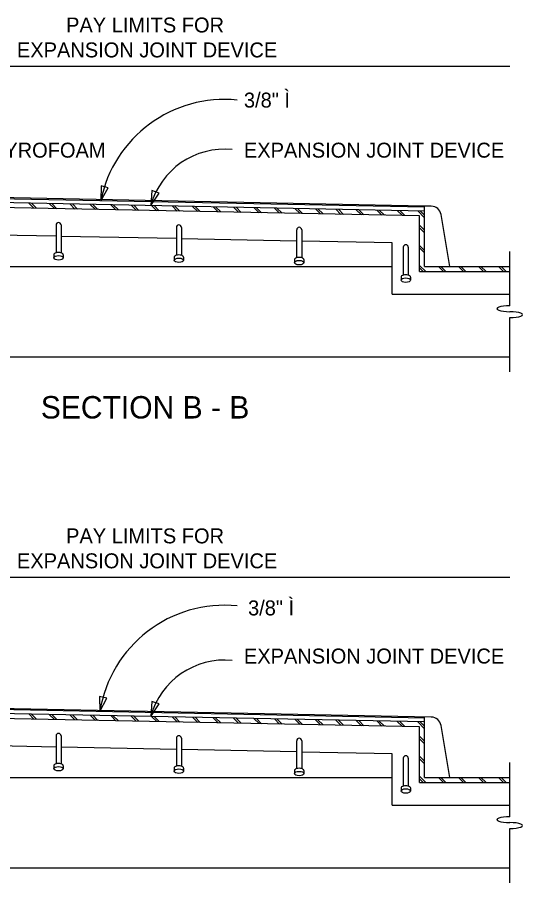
# Model space of a CAD drawing. Extents: x 19590 to 20151, y 19944 to 20103.
# Drawn here: x 19659.09 to 19674.83, y 20050.39 to 20077.38 of the extents above; entities that cross this region are included whole.
import ezdxf

# ---------------------------------------------------------------- set-up
doc = ezdxf.new("R2010")
doc.units = 0
doc.layers.add('DETAIL_PR', color=7, linetype='Continuous')
doc.layers.add('DETAIL_TEXT_DIMEN_PR', color=7, linetype='Continuous')

msp = doc.modelspace()

# ---------------------------------------------------------------- linework, layer by layer
at = {"layer": 'DETAIL_PR'}
for p, q in [((19671.778, 20071.498), (19655.216, 20071.829)), ((19671.778, 20071.459), (19655.216, 20071.79)), ((19671.778, 20071.342), (19655.216, 20071.673)), ((19671.622, 20071.188), (19655.216, 20071.517)), ((19659.605, 20071.429), (19659.446, 20071.588)), ((19659.685, 20071.427), (19659.525, 20071.587)), ((19660.243, 20071.416), (19660.083, 20071.576)), ((19660.323, 20071.414), (19660.163, 20071.574)), ((19660.881, 20071.403), (19660.721, 20071.563)), ((19660.96, 20071.402), (19660.801, 20071.561)), ((19661.518, 20071.391), (19661.359, 20071.55)), ((19661.598, 20071.389), (19661.439, 20071.548)), ((19662.156, 20071.378), (19661.997, 20071.537)), ((19662.236, 20071.376), (19662.076, 20071.536)), ((19662.794, 20071.365), (19662.634, 20071.524)), ((19662.874, 20071.363), (19662.714, 20071.523)), ((19663.432, 20071.352), (19663.272, 20071.512)), ((19663.511, 20071.351), (19663.352, 20071.51)), ((19664.069, 20071.34), (19663.91, 20071.499)), ((19664.149, 20071.338), (19663.99, 20071.497)), ((19664.707, 20071.327), (19664.548, 20071.486)), ((19664.787, 20071.325), (19664.627, 20071.485)), ((19665.345, 20071.314), (19665.185, 20071.473)), ((19665.425, 20071.312), (19665.265, 20071.472)), ((19665.983, 20071.301), (19665.823, 20071.461)), ((19666.062, 20071.3), (19665.903, 20071.459)), ((19666.62, 20071.288), (19666.461, 20071.448)), ((19666.7, 20071.287), (19666.541, 20071.446)), ((19667.258, 20071.276), (19667.099, 20071.435)), ((19667.338, 20071.274), (19667.178, 20071.434)), ((19667.896, 20071.263), (19667.736, 20071.422)), ((19667.976, 20071.261), (19667.816, 20071.421)), ((19668.534, 20071.25), (19668.374, 20071.41)), ((19668.613, 20071.249), (19668.454, 20071.408)), ((19671.778, 20069.607), (19671.778, 20071.498)), ((19671.987, 20071.494), (19671.778, 20071.498)), ((19669.171, 20071.237), (19669.012, 20071.397)), ((19669.251, 20071.236), (19669.092, 20071.395)), ((19669.809, 20071.225), (19669.65, 20071.384)), ((19669.889, 20071.223), (19669.729, 20071.383)), ((19670.447, 20071.212), (19670.287, 20071.371)), ((19670.528, 20071.209), (19670.367, 20071.37)), ((19671.085, 20071.199), (19670.925, 20071.359)), ((19671.164, 20071.198), (19671.005, 20071.357)), ((19671.778, 20071.131), (19671.563, 20071.346)), ((19671.622, 20069.451), (19671.622, 20071.188)), ((19671.778, 20071.209), (19671.643, 20071.344)), ((19672.289, 20071.232), (19672.559, 20069.607)), ((19660.293, 20070.906), (19660.293, 20070.037)), ((19660.449, 20070.906), (19660.449, 20070.037)), ((19671.778, 20070.74), (19671.622, 20070.896)), ((19660.293, 20070.555), (19656.7, 20070.627)), ((19664.042, 20070.831), (19664.042, 20069.962)), ((19664.198, 20070.831), (19664.198, 20069.962)), ((19667.791, 20070.756), (19667.791, 20069.887)), ((19667.948, 20070.756), (19667.948, 20069.887)), ((19671.778, 20070.662), (19671.622, 20070.818)), ((19664.042, 20070.481), (19660.449, 20070.552)), ((19667.791, 20070.406), (19664.198, 20070.477)), ((19670.763, 20070.346), (19667.948, 20070.402)), ((19670.763, 20068.748), (19670.763, 20070.346)), ((19671.114, 20070.211), (19671.114, 20069.341)), ((19671.27, 20070.211), (19671.27, 20069.341)), ((19671.778, 20070.115), (19671.622, 20070.271)), ((19671.778, 20070.037), (19671.622, 20070.193)), ((19674.434, 20068.385), (19674.434, 20070.076)), ((19660.223, 20069.977), (19660.223, 20069.881)), ((19660.52, 20069.977), (19660.52, 20069.881)), ((19663.972, 20069.902), (19663.972, 20069.806)), ((19664.269, 20069.902), (19664.269, 20069.806)), ((19667.721, 20069.827), (19667.721, 20069.731)), ((19668.018, 20069.827), (19668.018, 20069.731)), ((19650.919, 20069.607), (19670.763, 20069.607)), ((19671.817, 20069.451), (19671.622, 20069.646)), ((19671.739, 20069.451), (19671.622, 20069.568)), ((19671.778, 20069.607), (19674.434, 20069.607)), ((19672.364, 20069.451), (19672.208, 20069.607)), ((19672.442, 20069.451), (19672.286, 20069.607)), ((19672.989, 20069.451), (19672.833, 20069.607)), ((19673.067, 20069.451), (19672.911, 20069.607)), ((19673.614, 20069.451), (19673.458, 20069.607)), ((19673.692, 20069.451), (19673.536, 20069.607)), ((19674.239, 20069.451), (19674.083, 20069.607)), ((19674.317, 20069.451), (19674.161, 20069.607)), ((19671.044, 20069.282), (19671.044, 20069.186)), ((19671.341, 20069.282), (19671.341, 20069.186)), ((19671.622, 20069.451), (19674.434, 20069.451)), ((19670.763, 20068.748), (19674.434, 20068.748)), ((19674.434, 20066.326), (19674.434, 20068.017)), ((19651.7, 20066.795), (19674.434, 20066.795)), ((19671.987, 20055.556), (19656.231, 20055.871)), ((19671.778, 20055.521), (19656.231, 20055.832)), ((19671.622, 20055.251), (19656.075, 20055.562)), ((19671.778, 20055.404), (19656.231, 20055.715)), ((19659.605, 20055.491), (19659.446, 20055.651)), ((19659.685, 20055.49), (19659.525, 20055.649)), ((19660.243, 20055.479), (19660.083, 20055.638)), ((19660.323, 20055.477), (19660.163, 20055.636)), ((19660.881, 20055.466), (19660.721, 20055.625)), ((19660.96, 20055.464), (19660.801, 20055.624)), ((19661.518, 20055.453), (19661.359, 20055.612)), ((19661.598, 20055.451), (19661.439, 20055.611)), ((19662.156, 20055.44), (19661.997, 20055.6)), ((19662.236, 20055.439), (19662.076, 20055.598)), ((19662.794, 20055.428), (19662.634, 20055.587)), ((19662.874, 20055.426), (19662.714, 20055.585)), ((19663.432, 20055.415), (19663.272, 20055.574)), ((19663.511, 20055.413), (19663.352, 20055.573)), ((19664.069, 20055.402), (19663.91, 20055.561)), ((19664.149, 20055.4), (19663.99, 20055.56)), ((19664.707, 20055.389), (19664.548, 20055.549)), ((19664.787, 20055.388), (19664.627, 20055.547)), ((19665.345, 20055.376), (19665.185, 20055.536)), ((19665.425, 20055.375), (19665.265, 20055.534)), ((19665.983, 20055.364), (19665.823, 20055.523)), ((19666.062, 20055.362), (19665.903, 20055.522)), ((19666.62, 20055.351), (19666.461, 20055.51)), ((19666.7, 20055.349), (19666.541, 20055.509)), ((19667.258, 20055.338), (19667.099, 20055.498)), ((19667.338, 20055.337), (19667.178, 20055.496)), ((19667.896, 20055.325), (19667.736, 20055.485)), ((19667.976, 20055.324), (19667.816, 20055.483)), ((19668.534, 20055.313), (19668.374, 20055.472)), ((19671.778, 20053.67), (19671.778, 20055.56)), ((19668.613, 20055.311), (19668.454, 20055.471)), ((19669.171, 20055.3), (19669.012, 20055.459)), ((19669.251, 20055.298), (19669.092, 20055.458)), ((19669.809, 20055.287), (19669.65, 20055.447)), ((19669.889, 20055.286), (19669.729, 20055.445)), ((19670.447, 20055.274), (19670.287, 20055.434)), ((19670.528, 20055.271), (19670.367, 20055.432)), ((19671.085, 20055.262), (19670.925, 20055.421)), ((19671.164, 20055.26), (19671.005, 20055.42)), ((19671.778, 20055.193), (19671.563, 20055.408)), ((19671.622, 20053.513), (19671.622, 20055.251)), ((19671.778, 20055.271), (19671.643, 20055.407)), ((19672.289, 20055.295), (19672.559, 20053.67)), ((19660.293, 20054.968), (19660.293, 20054.099)), ((19660.449, 20054.968), (19660.449, 20054.099)), ((19671.778, 20054.803), (19671.622, 20054.959)), ((19660.293, 20054.618), (19656.7, 20054.69)), ((19664.042, 20054.893), (19664.042, 20054.024)), ((19664.198, 20054.893), (19664.198, 20054.024)), ((19667.791, 20054.818), (19667.791, 20053.949)), ((19667.948, 20054.818), (19667.948, 20053.949)), ((19671.778, 20054.724), (19671.622, 20054.881)), ((19664.042, 20054.543), (19660.449, 20054.615)), ((19667.791, 20054.468), (19664.198, 20054.54)), ((19670.763, 20054.409), (19667.948, 20054.465)), ((19670.763, 20052.81), (19670.763, 20054.409)), ((19671.114, 20054.274), (19671.114, 20053.403)), ((19671.27, 20054.274), (19671.27, 20053.403)), ((19671.778, 20054.178), (19671.622, 20054.334)), ((19671.778, 20054.099), (19671.622, 20054.256)), ((19674.434, 20052.448), (19674.434, 20054.138)), ((19660.223, 20054.039), (19660.223, 20053.943)), ((19660.52, 20054.039), (19660.52, 20053.943)), ((19663.972, 20053.964), (19663.972, 20053.868)), ((19664.269, 20053.964), (19664.269, 20053.868)), ((19667.721, 20053.889), (19667.721, 20053.793)), ((19668.018, 20053.889), (19668.018, 20053.793)), ((19651.231, 20053.67), (19670.763, 20053.67)), ((19671.817, 20053.514), (19671.622, 20053.709)), ((19671.739, 20053.514), (19671.622, 20053.631)), ((19671.778, 20053.67), (19674.434, 20053.67)), ((19672.364, 20053.514), (19672.208, 20053.67)), ((19672.442, 20053.514), (19672.286, 20053.67)), ((19672.989, 20053.514), (19672.833, 20053.67)), ((19673.067, 20053.514), (19672.911, 20053.67)), ((19673.614, 20053.514), (19673.458, 20053.67)), ((19673.692, 20053.514), (19673.536, 20053.67)), ((19674.239, 20053.514), (19674.083, 20053.67)), ((19674.317, 20053.514), (19674.161, 20053.67)), ((19671.044, 20053.345), (19671.044, 20053.249)), ((19671.341, 20053.345), (19671.341, 20053.249)), ((19671.622, 20053.513), (19674.434, 20053.513)), ((19670.763, 20052.81), (19674.434, 20052.81)), ((19674.434, 20050.388), (19674.434, 20052.079)), ((19651.7, 20050.857), (19674.434, 20050.857))]:
    msp.add_line(p, q, dxfattribs=at)
for centre, radius, start, end in [((19671.981, 20071.181), 0.313, 9.4315, 88.8542), ((19660.371, 20070.906), 0.0781, 0, 180), ((19664.121, 20070.831), 0.0781, 0, 180), ((19667.87, 20070.756), 0.0781, 0, 180), ((19671.192, 20070.211), 0.0781, 0, 180), ((19671.981, 20055.244), 0.313, 9.4315, 88.8542), ((19660.371, 20054.968), 0.0781, 0, 180), ((19664.121, 20054.893), 0.0781, 0, 180), ((19667.87, 20054.818), 0.0781, 0, 180), ((19671.192, 20054.273), 0.0781, 0, 180)]:
    msp.add_arc(centre, radius, start, end, dxfattribs=at)
for centre, major_axis, ratio, start_param, end_param in [((19660.371, 20069.977), (0.148, 0), 0.466726, 0, 3.141593), ((19664.121, 20069.902), (0.148, 0), 0.466726, 0, 3.141593), ((19667.87, 20069.827), (0.148, 0), 0.466726, 0, 3.141593), ((19671.192, 20069.282), (0.148, 0), 0.466726, 0, 3.141593), ((19674.434, 20068.293), (0.4, 0), 0.230204, 1.570796, 4.712389), ((19674.434, 20068.109), (0.4, 0), 0.230206, 4.712389, 7.853982), ((19660.371, 20054.039), (0.148, 0), 0.466726, 0, 3.141593), ((19664.121, 20053.964), (0.148, 0), 0.466726, 0, 3.141593), ((19667.87, 20053.889), (0.148, 0), 0.466726, 0, 3.141593), ((19671.192, 20053.345), (0.148, 0), 0.466726, 0, 3.141593), ((19674.434, 20052.356), (0.4, 0), 0.230204, 1.570796, 4.712389), ((19674.434, 20052.171), (0.4, 0), 0.230206, 4.712389, 7.853982)]:
    msp.add_ellipse(centre, major_axis=major_axis, ratio=ratio, start_param=start_param, end_param=end_param, dxfattribs=at)
for centre in [(19660.371, 20069.881), (19664.121, 20069.806), (19667.87, 20069.731), (19671.192, 20069.186), (19660.371, 20053.943), (19664.121, 20053.868), (19667.87, 20053.793), (19671.192, 20053.249)]:
    msp.add_ellipse(centre, major_axis=(0.148, 0), ratio=0.466726, dxfattribs=at)
at = {"layer": 'DETAIL_TEXT_DIMEN_PR'}
for p, q in [((19651.466, 20075.857), (19674.434, 20075.857)), ((19661.696, 20072.129), (19661.687, 20071.661)), ((19661.687, 20071.661), (19661.922, 20072.066)), ((19661.922, 20072.066), (19661.696, 20072.129)), ((19663.281, 20071.979), (19663.246, 20071.512)), ((19663.503, 20071.904), (19663.281, 20071.979)), ((19663.246, 20071.512), (19663.503, 20071.904)), ((19651.934, 20059.92), (19674.434, 20059.92)), ((19661.872, 20056.141), (19661.644, 20056.192)), ((19661.644, 20056.192), (19661.659, 20055.724)), ((19661.659, 20055.724), (19661.872, 20056.141)), ((19663.281, 20056.042), (19663.246, 20055.575)), ((19663.503, 20055.967), (19663.281, 20056.042)), ((19663.246, 20055.575), (19663.503, 20055.967))]:
    msp.add_line(p, q, dxfattribs=at)
for centre, radius, end in [((19665.542, 20070.892), 3.931, 168.7245), ((19665.542, 20070.892), 2.378, 164.8834), ((19665.542, 20055.111), 3.931, 171.0299), ((19665.542, 20054.955), 2.378, 164.8834)]:
    msp.add_arc(centre, radius, 84.1624, end, dxfattribs=at)

# ---------------------------------------------------------------- texts
for s, height, p in [('PAY LIMITS FOR', 0.46652, (19660.606, 20076.912)), ('EXPANSION JOINT DEVICE', 0.46652, (19659.075, 20076.134)), ('3/8" Ì', 0.4665, (19666.148, 20074.57)), ('3/4" STYROFOAM', 0.46652, (19656.622, 20073.007)), ('EXPANSION JOINT DEVICE', 0.46652, (19666.148, 20073.007)), ('SECTION B - B', 0.69987, (19659.818, 20064.869)), ('PAY LIMITS FOR', 0.46652, (19660.606, 20060.974)), ('EXPANSION JOINT DEVICE', 0.46652, (19659.075, 20060.196)), ('3/8" Ì', 0.4665, (19666.277, 20058.727)), ('EXPANSION JOINT DEVICE', 0.46652, (19666.148, 20057.226))]:
    msp.add_text(s, height=height, dxfattribs=at).set_placement(p)

doc.saveas('drawing.dxf')
